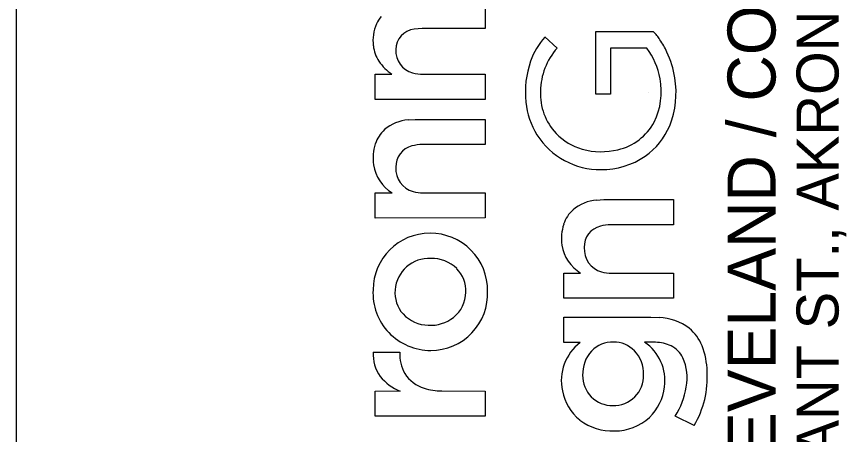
# Model space of a CAD drawing. Extents: x 2380994 to 2382560, y 256585 to 258122.
# Drawn here: x 2382520.03 to 2382539.71, y 257744.23 to 257754.14 of the extents above; entities that cross this region are included whole.
import ezdxf

# ---------------------------------------------------------------- set-up
doc = ezdxf.new("R2010")
doc.units = 0
doc.layers.add('RW_X_CL', color=7, linetype='Continuous')
doc.layers.add('SC_Scratch5', color=7, linetype='Continuous')

msp = doc.modelspace()

# ---------------------------------------------------------------- linework, layer by layer
at = {"layer": 'RW_X_CL'}
for p, q in [((2382531.146, 257754.451), (2382531.146, 257753.856)), ((2382529.649, 257753.855), (2382529.46, 257753.837)), ((2382531.146, 257753.856), (2382529.649, 257753.855)), ((2382532.559, 257753.652), (2382532.854, 257753.39)), ((2382533.768, 257753.779), (2382535.135, 257753.78)), ((2382533.768, 257752.297), (2382533.768, 257753.779)), ((2382534.121, 257753.39), (2382534.118, 257752.297)), ((2382534.979, 257753.387), (2382534.121, 257753.39)), ((2382528.54, 257752.172), (2382528.54, 257752.77)), ((2382528.54, 257752.77), (2382528.934, 257752.77)), ((2382529.673, 257752.77), (2382531.146, 257752.769)), ((2382531.146, 257752.769), (2382531.146, 257752.173)), ((2382534.118, 257752.297), (2382533.768, 257752.297)), ((2382535.031, 257752.342), (2382535.031, 257752.342)), ((2382531.146, 257752.173), (2382528.54, 257752.172)), ((2382529.319, 257751.689), (2382529.489, 257751.698)), ((2382529.489, 257751.698), (2382531.146, 257751.698)), ((2382531.146, 257751.698), (2382531.146, 257751.103)), ((2382531.146, 257751.103), (2382529.659, 257751.101)), ((2382528.54, 257749.955), (2382528.942, 257749.956)), ((2382528.54, 257749.359), (2382528.54, 257749.955)), ((2382529.676, 257749.956), (2382531.145, 257749.956)), ((2382531.145, 257749.956), (2382531.146, 257749.361)), ((2382533.788, 257749.786), (2382533.958, 257749.795)), ((2382533.958, 257749.795), (2382535.615, 257749.795)), ((2382535.615, 257749.795), (2382535.615, 257749.199)), ((2382531.146, 257749.361), (2382528.54, 257749.359)), ((2382535.615, 257749.199), (2382534.128, 257749.198)), ((2382533.009, 257748.052), (2382533.411, 257748.053)), ((2382533.009, 257747.456), (2382533.009, 257748.052)), ((2382534.145, 257748.053), (2382535.614, 257748.053)), ((2382535.614, 257748.053), (2382535.615, 257747.458)), ((2382535.615, 257747.458), (2382533.009, 257747.456)), ((2382533.009, 257746.409), (2382533.009, 257747.006)), ((2382533.009, 257747.006), (2382535.079, 257747.006)), ((2382535.079, 257747.006), (2382535.27, 257746.999)), ((2382533.399, 257746.409), (2382533.009, 257746.409)), ((2382535.184, 257746.413), (2382534.929, 257746.414)), ((2382528.491, 257746.181), (2382529.122, 257746.181)), ((2382528.54, 257745.257), (2382529.126, 257745.258)), ((2382528.54, 257744.66), (2382528.54, 257745.257)), ((2382530.114, 257745.258), (2382531.146, 257745.256)), ((2382531.146, 257745.256), (2382531.144, 257744.66)), ((2382531.144, 257744.66), (2382528.54, 257744.66)), ((2382536.103, 257744.44), (2382535.655, 257744.661))]:
    msp.add_line(p, q, dxfattribs=at)
for points in [[(2382529.675, 257754.452), (2382531.146, 257754.451), (2382531.146, 257753.856), (2382529.649, 257753.855), (2382529.46, 257753.837)], [(2382532.559, 257753.652), (2382532.854, 257753.39)], [(2382534.979, 257753.387), (2382534.121, 257753.39), (2382534.118, 257752.297), (2382533.768, 257752.297), (2382533.768, 257753.779), (2382535.135, 257753.78)], [(2382528.54, 257752.172), (2382528.54, 257752.77), (2382528.934, 257752.77)], [(2382529.673, 257752.77), (2382531.146, 257752.769), (2382531.146, 257752.173), (2382528.54, 257752.172)], [(2382529.319, 257751.689), (2382529.489, 257751.698), (2382531.146, 257751.698), (2382531.146, 257751.103), (2382529.659, 257751.101)], [(2382528.54, 257749.359), (2382528.54, 257749.955), (2382528.942, 257749.956)], [(2382529.676, 257749.956), (2382531.145, 257749.956), (2382531.146, 257749.361), (2382528.54, 257749.359)], [(2382533.788, 257749.786), (2382533.958, 257749.795), (2382535.615, 257749.795), (2382535.615, 257749.199), (2382534.128, 257749.198)], [(2382533.009, 257747.456), (2382533.009, 257748.052), (2382533.411, 257748.053)], [(2382534.145, 257748.053), (2382535.614, 257748.053), (2382535.615, 257747.458), (2382533.009, 257747.456)], [(2382533.399, 257746.409), (2382533.009, 257746.409), (2382533.009, 257747.006), (2382535.079, 257747.006), (2382535.27, 257746.999)], [(2382535.184, 257746.413), (2382534.929, 257746.414)], [(2382528.491, 257746.181), (2382529.122, 257746.181)], [(2382528.54, 257744.66), (2382528.54, 257745.257), (2382529.126, 257745.258)], [(2382530.114, 257745.258), (2382531.146, 257745.256), (2382531.144, 257744.66), (2382528.54, 257744.66)], [(2382536.103, 257744.44), (2382535.655, 257744.661)]]:
    msp.add_lwpolyline(points, dxfattribs=at)
for centre, radius, start, end in [((2382529.27, 257753.632), 0.775, 139.5245, 154.847), ((2382529.27, 257753.632), 0.775, 139.5245, 154.847), ((2382529.46, 257753.566), 0.975, 156.0638, 187.3493), ((2382529.46, 257753.566), 0.975, 156.0638, 187.3493), ((2382529.516, 257753.353), 0.487, 96.5532, 179.949), ((2382529.516, 257753.353), 0.487, 96.5532, 179.949), ((2382534.064, 257752.379), 1.971, 139.7948, 159.137), ((2382534.064, 257752.379), 1.971, 139.7948, 159.137), ((2382534.531, 257753.129), 0.888, 30.9891, 47.161), ((2382534.531, 257753.129), 0.888, 30.9891, 47.161), ((2382533.45, 257752.346), 2.221, 25.3031, 33.9618), ((2382533.45, 257752.346), 2.221, 25.3031, 33.9618), ((2382529.324, 257753.537), 0.836, 186.5579, 213.3885), ((2382529.324, 257753.537), 0.836, 186.5579, 213.3885), ((2382529.553, 257753.314), 0.526, 175.722, 255.7863), ((2382529.553, 257753.314), 0.526, 175.722, 255.7863), ((2382534.011, 257752.358), 1.551, 138.258, 179.7006), ((2382534.011, 257752.358), 1.551, 138.258, 179.7006), ((2382533.609, 257752.362), 1.711, 10.0751, 36.8319), ((2382533.609, 257752.362), 1.711, 10.0751, 36.8319), ((2382533.439, 257752.339), 2.233, 8.8034, 25.3348), ((2382533.439, 257752.339), 2.233, 8.8034, 25.3348), ((2382529.609, 257753.757), 1.196, 214.7043, 235.6872), ((2382529.609, 257753.757), 1.196, 214.7043, 235.6872), ((2382534.406, 257752.336), 2.307, 161.1438, 185.6281), ((2382534.406, 257752.336), 2.307, 161.1438, 185.6281), ((2382529.67, 257753.646), 0.876, 253.6672, 270.1498), ((2382529.67, 257753.646), 0.876, 253.6672, 270.1498), ((2382533.544, 257752.337), 2.13, 338.2887, 9.2855), ((2382533.544, 257752.337), 2.13, 338.2887, 9.2855), ((2382533.716, 257752.353), 1.607, 333.4669, 11.0367), ((2382533.716, 257752.353), 1.607, 333.4669, 11.0367), ((2382533.794, 257752.288), 1.335, 176.6658, 223.6912), ((2382533.794, 257752.288), 1.335, 176.6658, 223.6912), ((2382533.899, 257752.282), 1.797, 185.5077, 212.0129), ((2382533.899, 257752.282), 1.797, 185.5077, 212.0129), ((2382529.406, 257750.695), 0.998, 94.9706, 130.2248), ((2382529.406, 257750.695), 0.998, 94.9706, 130.2248), ((2382534.005, 257752.251), 1.304, 282.8815, 331.8147), ((2382534.005, 257752.251), 1.304, 282.8815, 331.8147), ((2382533.998, 257752.175), 1.648, 305.0306, 337.6757), ((2382533.998, 257752.175), 1.648, 305.0306, 337.6757), ((2382529.301, 257750.862), 0.803, 132.2238, 161.6823), ((2382529.301, 257750.862), 0.803, 132.2238, 161.6823), ((2382533.874, 257752.291), 1.782, 212.7022, 270.714), ((2382533.874, 257752.291), 1.782, 212.7022, 270.714), ((2382533.84, 257752.344), 1.408, 224.0215, 253.88), ((2382533.84, 257752.344), 1.408, 224.0215, 253.88), ((2382529.606, 257750.774), 1.12, 162.274, 187.7917), ((2382529.606, 257750.774), 1.12, 162.274, 187.7917), ((2382529.653, 257750.181), 0.92, 89.6051, 105.3303), ((2382529.653, 257750.181), 0.92, 89.6051, 105.3303), ((2382529.528, 257750.583), 0.5, 103.6868, 182.214), ((2382529.528, 257750.583), 0.5, 103.6868, 182.214), ((2382533.895, 257752.593), 1.662, 254.4535, 283.9512), ((2382533.895, 257752.593), 1.662, 254.4535, 283.9512), ((2382533.917, 257752.338), 1.828, 269.3273, 304.1963), ((2382533.917, 257752.338), 1.828, 269.3273, 304.1963), ((2382529.437, 257750.77), 0.953, 188.9646, 238.6987), ((2382529.437, 257750.77), 0.953, 188.9646, 238.6987), ((2382529.578, 257750.521), 0.551, 175.5844, 255.1382), ((2382529.578, 257750.521), 0.551, 175.5844, 255.1382), ((2382529.668, 257750.799), 0.843, 254.0891, 270.5284), ((2382529.668, 257750.799), 0.843, 254.0891, 270.5284), ((2382533.875, 257748.792), 0.998, 94.9706, 130.2248), ((2382533.875, 257748.792), 0.998, 94.9706, 130.2248), ((2382533.77, 257748.959), 0.803, 132.2238, 161.6823), ((2382533.77, 257748.959), 0.803, 132.2238, 161.6823), ((2382534.075, 257748.87), 1.12, 162.274, 187.7917), ((2382534.075, 257748.87), 1.12, 162.274, 187.7917), ((2382533.997, 257748.68), 0.5, 103.6868, 182.214), ((2382533.997, 257748.68), 0.5, 103.6868, 182.214), ((2382534.122, 257748.278), 0.92, 89.6051, 105.3303), ((2382534.122, 257748.278), 0.92, 89.6051, 105.3303), ((2382529.834, 257747.65), 1.348, 89.8476, 179.6405), ((2382529.834, 257747.65), 1.348, 89.8476, 179.6405), ((2382529.843, 257747.637), 1.362, 359.5401, 90.2114), ((2382529.843, 257747.637), 1.362, 359.5401, 90.2114), ((2382533.906, 257748.867), 0.953, 188.9646, 238.6987), ((2382533.906, 257748.867), 0.953, 188.9646, 238.6987), ((2382534.047, 257748.618), 0.551, 175.5844, 255.1382), ((2382534.047, 257748.618), 0.551, 175.5844, 255.1382), ((2382529.816, 257747.595), 0.808, 87.0481, 175.5726), ((2382529.816, 257747.595), 0.808, 87.0481, 175.5726), ((2382529.872, 257747.542), 0.86, 45.8426, 90.9801), ((2382529.872, 257747.542), 0.86, 45.8426, 90.9801), ((2382529.923, 257747.626), 0.764, 357.8857, 44.159), ((2382529.923, 257747.626), 0.764, 357.8857, 44.159), ((2382534.137, 257748.896), 0.843, 254.0891, 270.5284), ((2382534.137, 257748.896), 0.843, 254.0891, 270.5284), ((2382529.848, 257747.584), 1.364, 176.8344, 270.4038), ((2382529.848, 257747.584), 1.364, 176.8344, 270.4038), ((2382529.777, 257747.592), 0.77, 175.1538, 221.1471), ((2382529.777, 257747.592), 0.77, 175.1538, 221.1471), ((2382529.856, 257747.57), 1.35, 270.0624, 2.3776), ((2382529.856, 257747.57), 1.35, 270.0624, 2.3776), ((2382529.921, 257747.605), 0.766, 308.2894, 359.4347), ((2382529.921, 257747.605), 0.766, 308.2894, 359.4347), ((2382529.815, 257747.663), 0.846, 223.0999, 268.8089), ((2382529.815, 257747.663), 0.846, 223.0999, 268.8089), ((2382529.851, 257747.7), 0.884, 266.5651, 308.0608), ((2382529.851, 257747.7), 0.884, 266.5651, 308.0608), ((2382535.213, 257745.7), 1.301, 53.4034, 87.4906), ((2382535.213, 257745.7), 1.301, 53.4034, 87.4906), ((2382535.335, 257745.95), 1.028, 21.6075, 50.5577), ((2382535.335, 257745.95), 1.028, 21.6075, 50.5577), ((2382534.09, 257745.504), 1.138, 127.3748, 192.2247), ((2382534.09, 257745.504), 1.138, 127.3748, 192.2247), ((2382534.17, 257745.727), 0.692, 88.473, 136.4256), ((2382534.17, 257745.727), 0.692, 88.473, 136.4256), ((2382534.194, 257745.734), 0.685, 44.2719, 90.4762), ((2382534.194, 257745.734), 0.685, 44.2719, 90.4762), ((2382534.316, 257745.508), 1.094, 352.1125, 55.923), ((2382534.316, 257745.508), 1.094, 352.1125, 55.923), ((2382535.165, 257745.487), 0.927, 65.0169, 88.8011), ((2382535.165, 257745.487), 0.927, 65.0169, 88.8011), ((2382529.355, 257746.118), 0.866, 175.8731, 216.3475), ((2382529.355, 257746.118), 0.866, 175.8731, 216.3475), ((2382530.049, 257746.131), 0.928, 176.9688, 209.6064), ((2382530.049, 257746.131), 0.928, 176.9688, 209.6064), ((2382534.26, 257745.662), 0.802, 137.4674, 182.3324), ((2382534.26, 257745.662), 0.802, 137.4674, 182.3324), ((2382534.105, 257745.662), 0.799, 358.5714, 43.5376), ((2382534.105, 257745.662), 0.799, 358.5714, 43.5376), ((2382535.283, 257745.773), 0.617, 26.2681, 63.803), ((2382535.283, 257745.773), 0.617, 26.2681, 63.803), ((2382534.645, 257745.685), 1.767, 1.1514, 21.3627), ((2382534.645, 257745.685), 1.767, 1.1514, 21.3627), ((2382534.744, 257745.573), 1.191, 349.3073, 23.4307), ((2382534.744, 257745.573), 1.191, 349.3073, 23.4307), ((2382529.525, 257746.285), 1.102, 218.0981, 248.7907), ((2382529.525, 257746.285), 1.102, 218.0981, 248.7907), ((2382529.934, 257746.105), 0.816, 211.9447, 253.2028), ((2382529.934, 257746.105), 0.816, 211.9447, 253.2028), ((2382534.16, 257745.616), 0.702, 178.8821, 271.0837), ((2382534.16, 257745.616), 0.702, 178.8821, 271.0837), ((2382534.195, 257745.623), 0.709, 268.2788, 1.5502), ((2382534.195, 257745.623), 0.709, 268.2788, 1.5502), ((2382534.139, 257745.591), 2.277, 329.6388, 3.26), ((2382534.139, 257745.591), 2.277, 329.6388, 3.26), ((2382530.125, 257746.672), 1.414, 252.4655, 269.573), ((2382530.125, 257746.672), 1.414, 252.4655, 269.573), ((2382534.124, 257745.481), 1.167, 190.7518, 231.2892), ((2382534.124, 257745.481), 1.167, 190.7518, 231.2892), ((2382534.229, 257745.483), 1.177, 313.742, 353.8554), ((2382534.229, 257745.483), 1.177, 313.742, 353.8554), ((2382534.179, 257745.609), 1.754, 327.3149, 351.5748), ((2382534.179, 257745.609), 1.754, 327.3149, 351.5748), ((2382534.222, 257745.522), 1.21, 269.6361, 312.7088), ((2382534.222, 257745.522), 1.21, 269.6361, 312.7088), ((2382534.158, 257745.564), 1.254, 232.4606, 272.5902), ((2382534.158, 257745.564), 1.254, 232.4606, 272.5902)]:
    msp.add_arc(centre, radius, start, end, dxfattribs=at)
at = {"layer": 'SC_Scratch5'}
msp.add_line((2382520.031, 257692.342), (2382520.031, 258112.342), dxfattribs=at)

# ---------------------------------------------------------------- texts
at = {"layer": 'RW_X_CL'}
for s, height, p in [('450 GRANT ST., AKRON, OH  44311', 0.99692, (2382539.529, 257739.089)), ('AKRON / CLEVELAND / COLUMBUS', 1.13938, (2382538.034, 257735.102))]:
    msp.add_text(s, height=height, rotation=90, dxfattribs=at).set_placement(p)

doc.saveas('drawing.dxf')
